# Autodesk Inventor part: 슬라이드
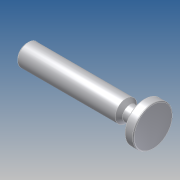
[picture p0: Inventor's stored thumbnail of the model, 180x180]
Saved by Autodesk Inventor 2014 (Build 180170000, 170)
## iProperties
Company: 한국ATC센터
Created: 2014-02
Part Number: 슬라이드
Document SubType Name: Modeling
Designer: KYOUNG IL JANG
Density: 7.86 g/cm^3
Mass: 68.0563 g
Surface Area: 34.7349 cm^2
Volume: 8.65856 cm^3
Material: 강, 연강
Vendor: CBT Solutions
Appearance: 강철
Author: KYOUNG IL JANG
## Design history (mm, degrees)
sketch "스케치1"
  geometry: L1 (-35, 0)-(35, 0); L2 (35, 0)-(35, 11); L3 (35, 11)-(30, 11); L4 (30, 11)-(30, 4); L5 (30, 4)-(22, 4); L6 (22, 4)-(20, 6); L7 (20, 6)-(-35, 6); L8 (-35, 6)-(-35, 0); 1 further point
  constraints: 16 end point, 4 parallel, 2 midpoint, 2 perpendicular, 1 horizontal
  dimensions: "d0" = 70 distance of L1.start L1.end; "d1" = 12 diameter of L7 L1; "d2" = 22 diameter of L3 L1; "d3" = 5 distance of L2.end L3.end; "d4" = 8 diameter of L5 L1; "d5" = 135 deg angle of L6 L5; "d6" = 15 distance from line of L2 L6.end
revolve "회전1" sketch "스케치1" stored, may be unused: angle "d7" = 90 deg
chamfer "모따기1" distance "d8" = 1; stored, may be unused: second distance "d9" = 2, angle "d10" = 45 deg
fillet "모깎기1" dims "d11" = 0.5
node "솔리드1"
